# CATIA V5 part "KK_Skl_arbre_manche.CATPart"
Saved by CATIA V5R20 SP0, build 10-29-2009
Part number: Skl_arbre_manche
Publications: "Point.1", "Point.2", "Point.3", "Plan_Ref1", "Droite.2", "Axe_pivot_manche_maneton", "Plan.Ref6"
Bounding box of the stored display mesh (mm): x -10 to 50, y 0 to 100, z 0 to 0
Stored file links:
  G:\Khaled_CFAO_2011\ST2M\ST2M_GR2\aandujar\Khaled\CAD_thinkMOTION\KK_Skl_arbre_manche.CATPart
  G:\Khaled_CFAO_2011\ST2M\ST2M_GR2\aandujar\Khaled\CAD_thinkMOTION\KK_Skl_scie_mecanique.CATProduct
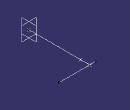
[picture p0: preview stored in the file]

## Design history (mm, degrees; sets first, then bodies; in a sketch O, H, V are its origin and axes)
Set1
  Point1 to Point3: linked copy from another document
  Plane1 "Plan_Ref1": linked copy from another document
  Plane2 "Plan.Ref6": linked copy from another document
Set2
  Line1: type PtDir, LineFirstUpto Point1, LineSecondUpto Point3, Direction Plane2, Start 0, End 50
  Line2 "Axe_pivot_manche_maneton": type Normal, RefPoint Point3, RefSkin Plane1, Start -10, End 50
Body1 (main body)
